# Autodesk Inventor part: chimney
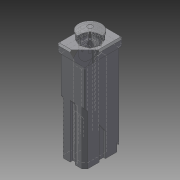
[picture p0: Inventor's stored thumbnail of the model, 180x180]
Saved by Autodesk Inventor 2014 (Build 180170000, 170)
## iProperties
Created: 2013-07
Part Number: chimney
Material: Generic
Document SubType Name: Modeling
Designer: Brent J. Rosenburgh
Density: 1 g/cm^3
Appearance: Default
Author: Brent J. Rosenburgh
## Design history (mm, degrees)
sketch "Sketch1"
  geometry: L1 (6.23, 11.74)-(-6.244, 11.74); L2 (-6.245, -11.748)-(-8.244, -9.708); L3 (-6.244, 11.74)-(-8.244, 9.74); L4 (8.23, 9.74)-(6.23, 11.74); L5 (6.23, -11.748)-(8.23, -9.748); L6 (-8.244, 2.133)-(-6.862, 2.133); L7 (-6.862, 2.133)-(-6.862, -0.609); L8 (-6.862, -0.609)-(-8.244, -1.991); L9 (8.23, 2.133)-(6.867, 2.133); L10 (6.867, 2.133)-(6.867, -0.609); L11 (6.867, -0.609)-(8.23, -1.972); L12 (-8.244, 9.74)-(-8.244, 2.133); L13 (-8.244, -1.991)-(-8.244, -9.708); L14 (8.23, -9.748)-(8.23, -1.972); L15 (8.23, 2.133)-(8.23, 9.74); L16 (-1.68, -11.748)-(-1.68, -9.875); L17 (-1.68, -9.875)-(1.667, -9.875); L18 (1.667, -9.875)-(1.667, -11.748); L19 (-6.245, -11.748)-(-1.68, -11.748); L20 (1.667, -11.748)-(6.23, -11.748); L21 (-2.966, 8.462)-(2.624, 8.462); L22 (4.624, 6.462)-(4.624, -6.141); L23 (2.624, -8.141)-(-2.966, -8.141); L24 (-4.966, -6.141)-(-4.966, 6.462); L25 (-2.966, 8.462)-(-4.966, 6.462); L26 (2.624, 8.462)-(4.624, 6.462); L27 (4.624, -6.141)-(2.624, -8.141); L28 (-2.966, -8.141)-(-4.966, -6.141); 1 further point
  constraints: 56 end point, 12 perpendicular, 11 parallel, 3 horizontal
extrude "Extrusion1" new body sketch "Sketch1" distance "d0" = 60; taper "d1" = 0 deg
sketch "Sketch2"
  geometry: L1 (-8.244, -9.708)-(-6.245, -11.748) reference; L2 (-1.68, -11.748)-(-1.68, -9.875) reference; L3 (-1.68, -9.875)-(1.667, -9.875) reference; L4 (1.667, -9.875)-(1.667, -11.748) reference; L5 (6.23, -11.748)-(8.23, -9.748) reference; L6 (-8.244, -1.991)-(-8.244, -9.708) reference; L7 (-8.244, -9.708)-(-8.244, -11.748); L8 (-8.244, -11.748)-(-6.245, -11.748); L9 (-1.68, -11.748)-(1.667, -11.748); L10 (6.23, -11.748)-(8.23, -11.748); L11 (8.23, -11.748)-(8.23, -9.748); 1 further point
  constraints: 10 end point, 3 collinear, 2 perpendicular
extrude "Extrusion2" join sketch "Sketch2" distance "d2" = 24; taper "d3" = 0 deg
chamfer "Chamfer2" distance "d7" = 1.8; stored, may be unused: second distance "d8" = 2, angle "d9" = 45 deg
sketch "Sketch3"
  geometry: L1 (0, 0)-(36, 0) reference; L2 (36, -2.04)-(36, 0) reference; L3 (36, -2.04)-(33.184, 0); 1 further point
  constraints: 2 end point, 1 point on line
extrude "Extrusion3" join sketch "Sketch3" distance "d10" = 16.47472; taper "d11" = 0 deg
sketch "Sketch4"
  geometry: L1 (8.23, -1.972)-(6.867, -0.609) reference; L2 (6.867, -0.609)-(6.867, 2.133) reference; L3 (6.867, 2.133)-(8.23, 2.133) reference; L4 (-8.244, 2.133)-(-6.862, 2.133) reference; L5 (-6.862, 2.133)-(-6.862, -0.609) reference; L6 (-6.862, -0.609)-(-8.244, -1.991) reference; L7 (-8.244, -1.991)-(-8.244, -11.748) reference; L8 (-8.244, 2.133)-(-8.244, -1.991); L9 (8.23, 2.133)-(8.23, -1.972); 1 further point
  constraints: 4 end point, 1 collinear, 1 parallel
extrude "Extrusion4" join sketch "Sketch4" distance "d12" = 38.02528; taper "d13" = 0 deg
sketch "Sketch5"
  geometry: L1 (33.184, 0)-(36, -2.04) reference; L2 (0, 11.841)-(21.975, 11.841) reference; L3 (21.975, 7.717)-(21.975, 11.841) reference; L4 (21.975, 7.717)-(16.281, 11.841); 1 further point
  constraints: 2 end point, 1 parallel, 1 point on line
extrude "Extrusion5" join sketch "Sketch5" distance "d14" = 2.22472; taper "d15" = 0 deg
sketch "Sketch6"
  geometry: L1 (-36, -2)-(-33.239, 0) reference; L2 (-21.975, 11.881)-(-21.975, 7.776) reference; L3 (0, 11.881)-(-21.975, 11.881) reference; L4 (-21.975, 7.776)-(-16.308, 11.881); 1 further point
  constraints: 2 end point, 1 parallel, 1 point on line
extrude "Extrusion6" join sketch "Sketch6" distance "d16" = 1.77528; taper "d17" = 0 deg
sketch "Sketch7"
  geometry: L1 (8.23, 9.74)-(6.23, 11.74) reference; L2 (-6.244, 11.74)-(-8.244, 9.74) reference; L3 (-8.244, 9.74)-(-8.244, -11.748) reference; L4 (-6.244, 11.74)-(-8.244, 11.74); L5 (-8.244, 11.74)-(-8.244, 9.74); L6 (6.23, 11.74)-(8.23, 11.74); L7 (8.23, 11.74)-(8.23, 9.74); 1 further point
  constraints: 8 end point, 4 perpendicular
extrude "Extrusion7" join sketch "Sketch7" distance "d18" = 54.47472; taper "d19" = 0 deg
sketch "Sketch8"
  geometry: L1 (5.525, 19.448)-(5.525, 21.448) reference; L2 (16.281, 11.841)-(21.975, 7.717) reference; L3 (0, 7.717)-(21.975, 7.717) reference; L4 (5.525, 19.448)-(2.764, 21.448); L5 (2.764, 21.448)-(5.525, 21.448); 1 further point
  constraints: 4 end point, 2 parallel
extrude "Extrusion8" join sketch "Sketch8" distance "d20" = 16.47472; taper "d21" = 0 deg
chamfer "Chamfer3" distance "d22" = 1.8; stored, may be unused: second distance "d23" = 2, angle "d24" = 45 deg
chamfer "Chamfer4" distance "d25" = 1.4; stored, may be unused: second distance "d26" = 2, angle "d27" = 45 deg
chamfer "Chamfer5" distance "d28" = 0.5; stored, may be unused: second distance "d29" = 2, angle "d30" = 45 deg
sketch "Sketch9"
  geometry: L1 (7.73, 11.74)-(8.23, 11.24) reference; L2 (7.73, 11.74)-(-7.744, 11.74) reference; L3 (-8.244, 11.24)-(-7.744, 11.74) reference; L4 (-8.244, 11.24)-(-8.244, -11.248) reference; L5 (-7.744, -11.748)-(-8.244, -11.248) reference; L6 (-7.744, -11.748)-(7.73, -11.748) reference; L7 (8.23, -11.248)-(7.73, -11.748) reference; L8 (8.23, -11.248)-(8.23, 11.24) reference; 1 further point
extrude "Extrusion9" join sketch "Sketch9" distance "d31" = 1.47472; taper "d32" = 45 deg
sketch "Sketch10"
  geometry: L1 (9.705, 11.851)-(9.705, -11.859) reference; L2 (8.341, 13.215)-(9.705, 11.851) reference; L3 (-8.355, 13.215)-(8.341, 13.215) reference; L4 (-9.719, 11.851)-(-8.355, 13.215) reference; L5 (-9.719, -11.859)-(-9.719, 11.851) reference; L6 (-8.355, -13.223)-(-9.719, -11.859) reference; L7 (8.341, -13.223)-(-8.355, -13.223) reference; L8 (9.705, -11.859)-(8.341, -13.223) reference; 1 further point
extrude "Extrusion10" join sketch "Sketch10" distance "d33" = 4; taper "d34" = 0 deg
sketch "Sketch11"
  geometry: L1 (9.705, -11.859)-(9.705, 11.851) reference; L2 (9.705, 11.851)-(8.341, 13.215) reference; L3 (8.341, 13.215)-(-8.355, 13.215) reference; L4 (-8.355, 13.215)-(-9.719, 11.851) reference; L5 (-9.719, 11.851)-(-9.719, -11.859) reference; L6 (-9.719, -11.859)-(-8.355, -13.223) reference; L7 (-8.355, -13.223)-(8.341, -13.223) reference; L8 (8.341, -13.223)-(9.705, -11.859) reference; 1 further point
extrude "Extrusion11" join sketch "Sketch11" distance "d35" = 1; taper "d36" = -45 deg
sketch "Sketch12"
  geometry: C1 r 5.597 at (0, 0); 1 further point
  constraints: 1 centre point, 1 coincident
extrude "Extrusion12" cut sketch "Sketch12" distance "d37" = 6.5; taper "d38" = 0 deg
chamfer "Chamfer6" distance "d39" = 0.5; stored, may be unused: second distance "d40" = 2, angle "d41" = 45 deg
chamfer "Chamfer7" distance "d42" = 5.5; stored, may be unused: second distance "d43" = 2, angle "d44" = 45 deg
chamfer "Chamfer8" distance "d45" = 5.75; stored, may be unused: second distance "d46" = 2, angle "d47" = 45 deg
sketch "Sketch13"
  geometry: L1 (0.5, -7)-(-0.5, -7); L2 (-0.5, -7)-(-0.5, 7); L3 (-0.5, 7)-(0.5, 7); L4 (0.5, 7)-(0.5, -7); L5 (0.5, -7)-(-0.5, 7); L6 (-0.5, -7)-(0.5, 7); L7 (-7, -0.5)-(7, -0.5); L8 (7, -0.5)-(7, 0.5); L9 (7, 0.5)-(-7, 0.5); L10 (-7, 0.5)-(-7, -0.5); L11 (4.596, -5.303)-(5.303, -4.596); L12 (5.303, -4.596)-(-4.596, 5.303); L13 (-5.303, 4.596)-(4.596, -5.303); L14 (-4.596, 5.303)-(-5.303, 4.596); L15 (4.596, 5.303)-(-5.303, -4.596); L16 (-5.303, -4.596)-(-4.596, -5.303); L17 (-4.596, -5.303)-(5.303, 4.596); L18 (5.303, 4.596)-(4.596, 5.303); C1 r 5.597 at (0, 0) reference
  constraints: 36 end point, 8 parallel, 4 perpendicular, 2 horizontal, 2 midpoint
  dimensions: "d48" = 1 distance of L2.end L3.end
extrude "Extrusion13" join sketch "Sketch13" distance "d49" = 4; taper "d50" = 0 deg
chamfer "Chamfer9" distance "d51" = 4.25; stored, may be unused: second distance "d52" = 2, angle "d53" = 45 deg
chamfer "Chamfer10" distance "d54" = 1; stored, may be unused: second distance "d55" = 2, angle "d56" = 45 deg
sketch "Sketch14"
  geometry: C1 r 7.018 at (0, 0); 1 further point
  constraints: 1 centre point, 1 coincident
extrude "Extrusion14" join sketch "Sketch14" distance "d57" = 0.6; taper "d58" = 45 deg
sketch "Sketch15"
  geometry: C1 r 7.618 at (0, 0) reference
extrude "Extrusion15" join sketch "Sketch15" distance "d59" = 1; taper "d60" = 0 deg
sketch "Sketch16"
  geometry: C1 r 7.618 at (0, 0) reference
extrude "Extrusion16" join sketch "Sketch16" distance "d61" = 2; taper "d62" = 0 deg
chamfer "Chamfer11" distance "d63" = 6; stored, may be unused: second distance "d64" = 2, angle "d65" = 45 deg
body "Solid1"
